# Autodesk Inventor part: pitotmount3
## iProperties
Created: 2010-03
Part Number: pitotmount3
Document SubType Name: Modeling
Designer: a31883
Density: 1 g/cm^3
Author: a31883
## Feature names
1. Extrusion1
